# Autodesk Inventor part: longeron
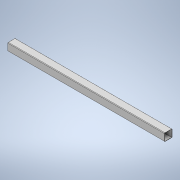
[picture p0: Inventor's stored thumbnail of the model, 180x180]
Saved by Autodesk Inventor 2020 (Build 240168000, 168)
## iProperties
Created: 2021-01
Part Number: longeron
Material: Générique
Document SubType Name: Modeling
Designer: bruno
Density: 1 g/cm^3
Appearance: Par défaut
Author: bruno
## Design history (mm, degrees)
sketch "Esquisse1"
  geometry: L1 (2, 0)-(28, 0); L2 (30, -2)-(30, -28); L3 (28, -30)-(2, -30); L4 (0, -28)-(0, -2); L5 (29, -28)-(29, -2); L6 (28, -1)-(2, -1); L7 (1, -2)-(1, -28); L8 (2, -29)-(28, -29); A1 r 2 centre (28, -28) between (28, -30) and (30, -28); A2 r 2 centre (28, -2) between (30, -2) and (28, 0); A3 r 2 centre (2, -2) between (2, 0) and (0, -2); A4 r 2 centre (2, -28) between (0, -28) and (2, -30); A5 r 1 centre (28, -2) between (29, -2) and (28, -1); A6 r 1 centre (2, -2) between (2, -1) and (1, -2); A7 r 1 centre (2, -28) between (1, -28) and (2, -29); A8 r 1 centre (28, -28) between (28, -29) and (29, -28); 4 further points
  constraints: 16 end point, 16 point on circle, 8 centre point, 8 point on line, 8 tangent, 4 parallel, 3 equal radius, 2 perpendicular, 1 horizontal, 7 other
  dimensions: "d0" = 30 distance of point (30, -30) point (0, -30); "d1" = 30 distance of point (30, 0) point (30, -30); "d2" = 2 radius of A1 (derived); "d3" = 1 distance between parallel lines of L2 L5
extrude "Extrusion1" new body sketch "Esquisse1" distance "d4" = 615; taper "d5" = 0 deg
node "Solide1"
